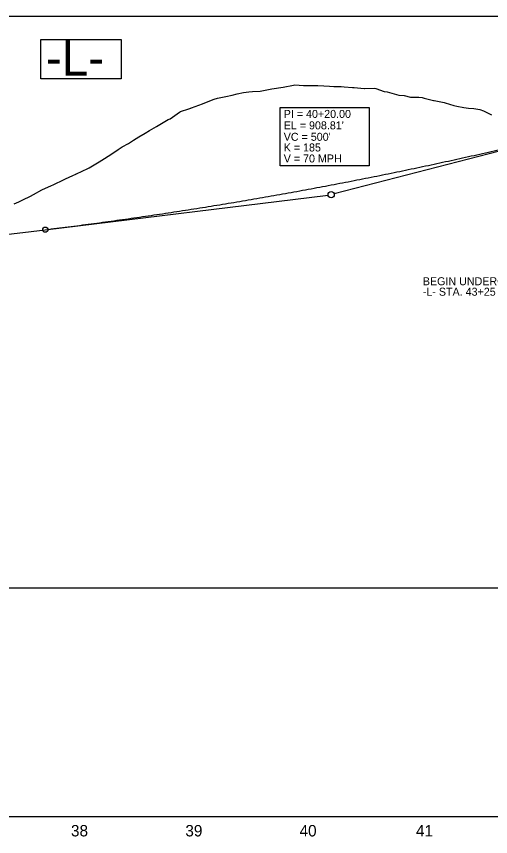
# Model space of a CAD drawing. Extents: x 1968019 to 1983409, y 545058 to 567558.
# Drawn here: x 1971588 to 1972002, y 566291 to 567008 of the extents above; entities that cross this region are included whole.
import ezdxf

# ---------------------------------------------------------------- set-up
doc = ezdxf.new("R2010")
doc.units = 0
for name, color, linetype in [('Exist Profile Cell', 7, 'Continuous'), ('Exist Vertical Profile Ground Line', 7, 'Continuous'), ('Exist Vertical Profile Horizontal Axis Label Major', 7, 'Continuous'), ('Old_Level_1', 7, 'Continuous'), ('Prop Grid Mask', 7, 'Continuous'), ('Prop Road Sect_ Recs - UC (Tx)', 7, 'Continuous'), ('Prop Vertical Profile Curve Label', 7, 'Continuous'), ('Prop Vertical Profile Grade', 7, 'Continuous'), ('Prop VPI Label', 7, 'Continuous'), ('Scratch_Level_8', 7, 'Continuous')]:
    doc.layers.add(name, color=color, linetype=linetype)

msp = doc.modelspace()

# ---------------------------------------------------------------- linework, layer by layer
at = {"layer": 'Exist Profile Cell'}
msp.add_line((1968842.96, 566308.43), (1972642.96, 566308.43), dxfattribs=at)
at = {"layer": 'Exist Vertical Profile Ground Line'}
for points in [[(1971740.5, 566928.3), (1971740.75, 566928.4), (1971750.56, 566932.06), (1971758.36, 566935.23), (1971760.63, 566936.04), (1971763.5, 566936.82), (1971770.7, 566938.47), (1971776.36, 566939.52), (1971780.77, 566940.72), (1971786.42, 566941.85), (1971790.85, 566942.34), (1971794.3, 566942.63), (1971800.93, 566943.15), (1971809.51, 566944.69), (1971811.01, 566944.95), (1971820.97, 566946.42), (1971821.09, 566946.44), (1971821.1, 566946.44), (1971829.98, 566948.3), (1971831.19, 566948.43), (1971838.87, 566947.88), (1971841.28, 566948.08), (1971847.74, 566948.08), (1971851.38, 566948.07), (1971856.59, 566947.8), (1971861.48, 566947.37), (1971865.43, 566947.23), (1971871.58, 566947.11), (1971874.25, 566946.76), (1971881.69, 566946.29), (1971883.06, 566946.17), (1971891.8, 566945.33), (1971892.23, 566945.35), (1971900.64, 566945.64), (1971901.92, 566945.4), (1971909.41, 566942.83), (1971912.04, 566942.54), (1971918.16, 566940.76), (1971922.16, 566939.47), (1971926.9, 566939.1), (1971932.29, 566937.65), (1971939.75, 566937.81), (1971942.42, 566937.37), (1971944.34, 566936.78), (1971952.56, 566934.91), (1971953.04, 566934.87), (1971955.92, 566934.3), (1971961.72, 566933.17), (1971962.7, 566932.94), (1971970.39, 566930.56), (1971972.84, 566929.91), (1971979.05, 566928.6), (1971982.99, 566928.25), (1971987.7, 566927.81), (1971993.14, 566926.89), (1971996.33, 566925.79), (1972003.3, 566922.2)], [(1971585.76, 566844.56), (1971589.83, 566846.27), (1971593.34, 566847.88), (1971599.86, 566851.15), (1971602.66, 566852.71), (1971609.89, 566856.61), (1971618.37, 566860.46), (1971619.92, 566861.15), (1971629.31, 566865.69), (1971629.96, 566865.98), (1971630.5, 566866.23), (1971636.91, 566869.15), (1971639.75, 566870.43), (1971640, 566870.55), (1971640.29, 566870.72), (1971650.04, 566875.42), (1971651.3, 566876.07), (1971660.08, 566881.32), (1971662.35, 566882.64), (1971670.12, 566887.55), (1971676.55, 566892.04), (1971680.17, 566894.24), (1971685.71, 566897.23), (1971690.22, 566900.16), (1971694.85, 566903.13), (1971700.27, 566906.19), (1971703.97, 566908.45), (1971710.32, 566912.16), (1971713.08, 566913.7), (1971720.38, 566918.13), (1971722.17, 566918.76), (1971730.43, 566924.7), (1971731.24, 566925.28), (1971738.51, 566927.63), (1971740.3, 566928.22), (1971740.5, 566928.3)]]:
    msp.add_lwpolyline(points, dxfattribs=at)
at = {"layer": 'Prop Grid Mask'}
for points in [[(1971609.07, 566988.3), (1971679.21, 566988.3), (1971679.21, 566953.74), (1971609.07, 566953.74)], [(1971818.22, 566928.66), (1971896.3, 566928.66), (1971896.3, 566877.63), (1971818.22, 566877.63)]]:
    msp.add_lwpolyline(points, close=True, dxfattribs=at)
at = {"layer": 'Prop Vertical Profile Curve Label'}
msp.add_circle((1971612.96, 566821.8), 2.25, dxfattribs=at)
at = {"layer": 'Prop Vertical Profile Grade'}
msp.add_line((1970942.96, 566739.6), (1971612.96, 566821.8), dxfattribs=at)
msp.add_spline([(1971612.96, 566821.8), (1971622.96, 566823.04), (1971632.96, 566824.31), (1971642.96, 566825.61), (1971652.96, 566826.93), (1971662.96, 566828.28), (1971672.96, 566829.65), (1971682.96, 566831.05), (1971692.96, 566832.49), (1971702.96, 566833.94), (1971712.96, 566835.43), (1971722.96, 566836.94), (1971732.96, 566838.48), (1971742.96, 566840.04), (1971752.96, 566841.63), (1971762.96, 566843.25), (1971772.96, 566844.9), (1971782.96, 566846.58), (1971792.96, 566848.28), (1971802.96, 566850), (1971812.96, 566851.76), (1971822.96, 566853.54), (1971832.96, 566855.35), (1971842.96, 566857.19), (1971852.96, 566859.05), (1971862.96, 566860.94), (1971872.96, 566862.86), (1971882.96, 566864.8), (1971892.96, 566866.78), (1971902.96, 566868.78), (1971912.96, 566870.8), (1971922.96, 566872.86), (1971932.96, 566874.94), (1971942.96, 566877.04), (1971952.96, 566879.18), (1971962.96, 566881.34), (1971972.96, 566883.53), (1971982.96, 566885.74), (1971992.96, 566887.99), (1972002.96, 566890.26), (1972012.96, 566892.55), (1972022.96, 566894.88), (1972032.96, 566897.23), (1972042.96, 566899.61), (1972052.96, 566902.01), (1972062.96, 566904.44), (1972072.96, 566906.9), (1972082.96, 566909.39), (1972092.96, 566911.9), (1972102.96, 566914.45), (1972112.96, 566917.01)], degree=3, dxfattribs=at)
at = {"layer": 'Prop VPI Label'}
for p, q in [((1972112.96, 566917.01), (1971865.62, 566853.16)), ((1971612.96, 566821.8), (1971860.23, 566852.14))]:
    msp.add_line(p, q, dxfattribs=at)
msp.add_circle((1971862.96, 566852.48), 2.75, dxfattribs=at)
at = {"layer": 'Scratch_Level_8'}
msp.add_lwpolyline([(1970942.96, 566508.43), (1972342.96, 566508.43), (1972342.96, 567008.43), (1970942.96, 567008.43)], close=True, dxfattribs=at)

# ---------------------------------------------------------------- texts
at = {"layer": 'Exist Vertical Profile Horizontal Axis Label Major'}
for s, p in [('38', (1971635.42, 566290.93)), ('39', (1971735.47, 566290.93)), ('40', (1971835.34, 566290.93)), ('41', (1971937.18, 566290.93))]:
    msp.add_text(s, height=10, dxfattribs=at).set_placement(p)
at = {"layer": 'Old_Level_1'}
msp.add_text('-L-', height=31.25, dxfattribs=at).set_placement((1971613.38, 566956.71))
at = {"layer": 'Prop Road Sect_ Recs - UC (Tx)'}
for s, p in [('BEGIN UNDERCUT FOR SUBGRADE STABILITY', (1971943.14, 566773.19)), ('-L- STA. 43+25 +/-', (1971943.14, 566764.02))]:
    msp.add_text(s, height=7, dxfattribs=at).set_placement(p)
at = {"layer": 'Prop Vertical Profile Curve Label'}
for s, p in [("VC = 500'", (1971821.47, 566899.59)), ('K = 185', (1971821.47, 566890.25)), ('V = 70 MPH', (1971821.47, 566880.62))]:
    msp.add_text(s, height=7, dxfattribs=at).set_placement(p)
at = {"layer": 'Prop VPI Label'}
for s, p in [('PI = 40+20.00', (1971821.47, 566919.59)), ("EL = 908.81'", (1971821.47, 566909.59))]:
    msp.add_text(s, height=7, dxfattribs=at).set_placement(p)

doc.saveas('drawing.dxf')
